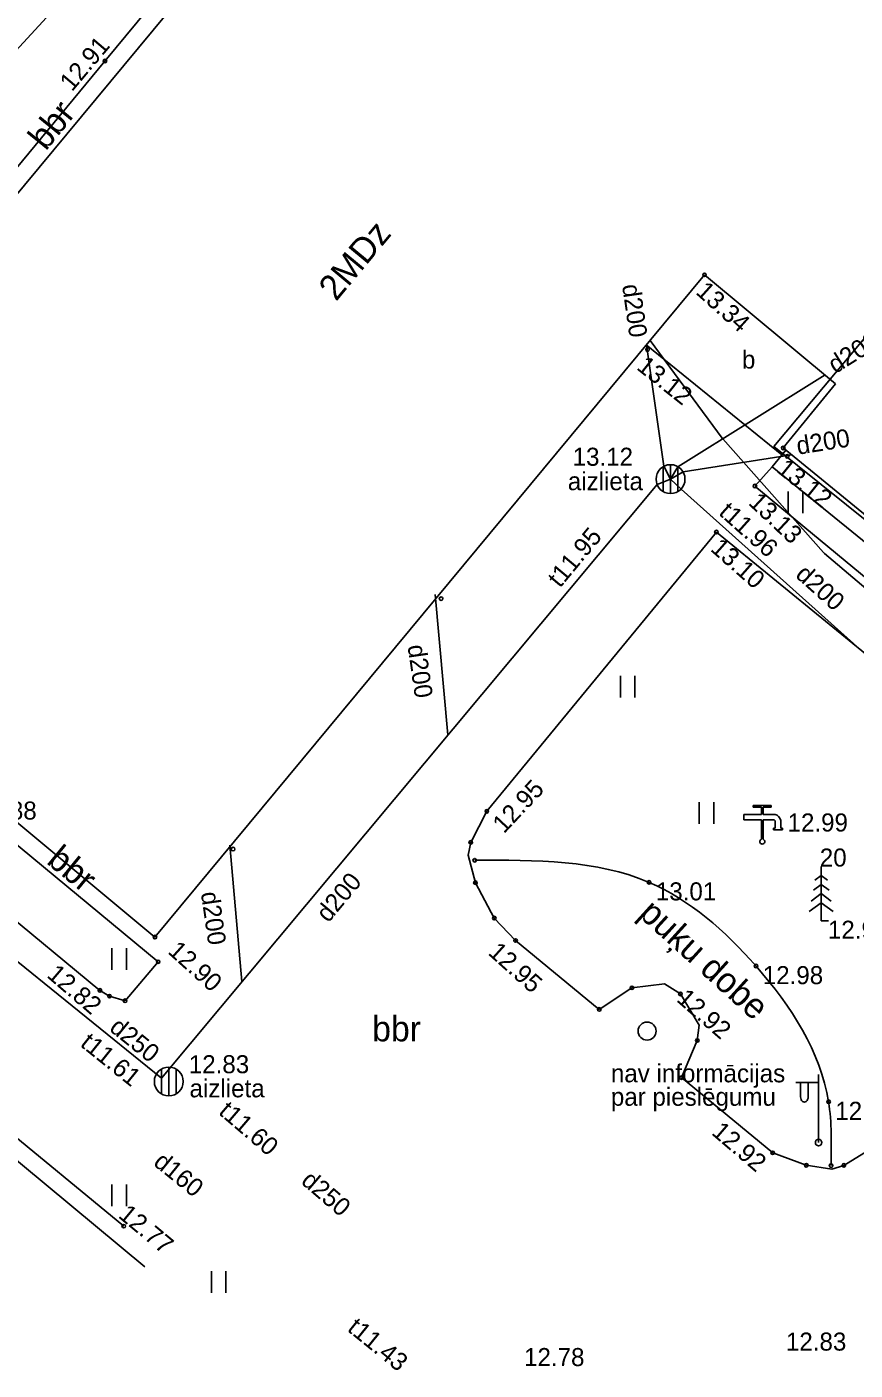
# Model space of a CAD drawing. Extents: x 503877 to 504025, y 304562 to 304725.
# Drawn here: x 503910.05 to 503933, y 304561.87 to 304599.07 of the extents above; entities that cross this region are included whole.
import ezdxf

# ---------------------------------------------------------------- set-up
doc = ezdxf.new("R2010")
doc.units = 0
for name, color, linetype in [('42', 7, 'Continuous'), ('APGS_ELEM_####_####_#', 7, 'Continuous'), ('APGS_ELEM_####_TKST_#', 7, 'Continuous'), ('BUVE_BDET_####_####_#', 7, 'Continuous'), ('BUVE_BDET_####_TKST_#', 7, 'Continuous'), ('BUVE_EKAS_####_####_#', 7, 'Continuous'), ('BUVE_EKAS_ADRS_TKST_#', 7, 'Continuous'), ('BUVE_ELEM_####_####_#', 7, 'Continuous'), ('CELI_CMAL_####_####_#', 7, 'Continuous'), ('CELI_CSEG_####_TKST_#', 7, 'Continuous'), ('ELEK_VADP_ZSPR_####_#', 7, 'Continuous'), ('LKAN_ELEM_####_####_#', 7, 'Continuous'), ('LKAN_ELEM_PAST_TKST_#', 7, 'Continuous'), ('LKAN_VADP_PAST_####_#', 7, 'Continuous'), ('LKAN_VADP_PAST_TKST_#', 7, 'Continuous'), ('RELJ_AATZ_####_TKST_#', 7, 'Continuous'), ('RELJ_ELEM_####_####_#', 7, 'Continuous'), ('SKAN_ELEM_PAST_TKST_#', 7, 'Continuous'), ('SKAN_VADP_PAST_TKST_#', 7, 'Continuous'), ('TERT_DIAM_####_TKST_#', 7, 'Continuous'), ('TERT_ELEM_####_####_#', 7, 'Continuous'), ('TERT_IZMT_####_TKST_#', 7, 'Continuous'), ('TERT_KONT_####_####_#', 7, 'Continuous'), ('UDTK_ELEM_####_####_#', 7, 'Continuous'), ('UDTK_ELEM_####_TKST_#', 7, 'Continuous')]:
    doc.layers.add(name, color=color, linetype=linetype)

msp = doc.modelspace()

# ---------------------------------------------------------------- linework, layer by layer
at = {"layer": '42'}
msp.add_lwpolyline([(503940.294, 304598.947), (503951.661, 304589.773), (503949.864, 304587.645), (503954.733, 304583.621), (503953.927, 304582.557), (503960.49, 304577.208), (503958.987, 304575.41), (503959.865, 304574.697), (503955.838, 304569.828), (503955.063, 304570.502), (503953.67, 304568.891), (503946.74, 304574.542), (503947.217, 304575.092), (503942.561, 304578.835), (503942.084, 304578.358), (503930.754, 304587.457), (503939.344, 304597.708)], close=True, dxfattribs=at)
at = {"layer": 'APGS_ELEM_####_####_#'}
for p, q in [((503931.992, 304569.841), (503931.357, 304569.836)), ((503931.492, 304569.837), (503931.492, 304569.445)), ((503931.702, 304569.839), (503931.702, 304569.445)), ((503931.992, 304568.174), (503931.992, 304570.057))]:
    msp.add_line(p, q, dxfattribs=at)
msp.add_circle((503931.992, 304568.174), 0.09, dxfattribs=at)
msp.add_ellipse((503931.597, 304569.445), major_axis=(0, 0.151), ratio=0.695971, start_param=1.570796, end_param=4.712389, dxfattribs=at)
at = {"layer": 'BUVE_BDET_####_####_#'}
for p, q in [((503930.975, 304587.224), (503927.218, 304590.266)), ((503931.081, 304587.355), (503930.703, 304586.889)), ((503941.788, 304577.888), (503930.703, 304586.889))]:
    msp.add_line(p, q, dxfattribs=at)
at = {"layer": 'BUVE_EKAS_####_####_#'}
for p, q in [((503924.556, 304612.247), (503901.224, 304584.141)), ((503913.603, 304573.865), (503928.83, 304592.208)), ((503932.464, 304589.191), (503928.83, 304592.208)), ((503932.464, 304589.191), (503931.011, 304587.412)), ((503942.277, 304578.21), (503931.011, 304587.412)), ((503908.794, 304577.857), (503913.603, 304573.865)), ((503904.187, 304572.307), (503913.325, 304564.734))]:
    msp.add_line(p, q, dxfattribs=at)
at = {"layer": 'BUVE_ELEM_####_####_#'}
msp.add_circle((503927.24, 304571.263), 0.25, dxfattribs=at)
at = {"layer": 'CELI_CMAL_####_####_#'}
for p, q in [((503912.215, 304598.126), (503924.433, 304612.895)), ((503921.326, 304610.998), (503899.68, 304587.482)), ((503901.003, 304584.612), (503912.215, 304598.126)), ((503930.227, 304586.356), (503930.703, 304586.889)), ((503941.255, 304577.235), (503930.227, 304586.356)), ((503922.799, 304577.351), (503929.16, 304585.083)), ((503929.16, 304585.083), (503940.23, 304576.035)), ((503913.691, 304573.18), (503906.103, 304579.453)), ((503904.812, 304578.39), (503912.077, 304572.389)), ((503922.799, 304577.351), (503922.354, 304576.49)), ((503922.354, 304576.49), (503922.28, 304576.131)), ((503922.28, 304576.131), (503922.483, 304575.373)), ((503922.483, 304575.373), (503923.005, 304574.392)), ((503923.005, 304574.392), (503923.594, 304573.772)), ((503923.594, 304573.772), (503925.914, 304571.863)), ((503912.775, 304572.103), (503913.691, 304573.18)), ((503904.097, 304572.983), (503912.739, 304565.859)), ((503912.077, 304572.389), (503912.343, 304572.23)), ((503925.914, 304571.863), (503926.818, 304572.461)), ((503926.818, 304572.461), (503927.723, 304572.575)), ((503927.723, 304572.575), (503928.164, 304572.292)), ((503912.343, 304572.23), (503912.775, 304572.103)), ((503928.164, 304572.292), (503928.678, 304571.43)), ((503928.678, 304571.43), (503928.63, 304571.001)), ((503928.63, 304571.001), (503928.192, 304569.973)), ((503930.721, 304567.89), (503928.192, 304569.973)), ((503933.951, 304568.323), (503932.691, 304567.544)), ((503931.65, 304567.547), (503930.721, 304567.89)), ((503932.362, 304567.437), (503931.65, 304567.547)), ((503932.691, 304567.544), (503932.362, 304567.437))]:
    msp.add_line(p, q, dxfattribs=at)
at = {"layer": 'ELEK_VADP_ZSPR_####_#'}
for p, q in [((503929.324, 304587.688), (503927.329, 304590.386)), ((503929.341, 304587.667), (503929.324, 304587.688)), ((503932.126, 304584.518), (503929.341, 304587.667)), ((503932.157, 304584.487), (503932.126, 304584.518)), ((503942.397, 304575.823), (503932.157, 304584.487))]:
    msp.add_line(p, q, dxfattribs=at)
at = {"layer": 'LKAN_ELEM_####_####_#'}
for p, q in [((503927.689, 304586.203), (503927.689, 304586.895)), ((503927.889, 304586.149), (503927.889, 304586.949)), ((503928.089, 304586.203), (503928.089, 304586.895)), ((503913.786, 304569.52), (503913.786, 304570.212)), ((503913.986, 304569.466), (503913.986, 304570.266)), ((503914.186, 304569.52), (503914.186, 304570.212))]:
    msp.add_line(p, q, dxfattribs=at)
for centre in [(503927.889, 304586.549), (503913.986, 304569.866)]:
    msp.add_circle(centre, 0.4, dxfattribs=at)
at = {"layer": 'LKAN_VADP_PAST_####_#'}
for p, q in [((503927.704, 304586.904), (503927.221, 304590.267)), ((503928.094, 304586.893), (503932.17, 304589.435)), ((503927.704, 304586.904), (503927.889, 304586.549)), ((503927.889, 304586.549), (503928.094, 304586.893)), ((503931.24, 304587.225), (503928.235, 304586.75)), ((503927.516, 304586.405), (503927.889, 304586.549)), ((503927.889, 304586.549), (503928.235, 304586.75)), ((503927.889, 304586.549), (503928.18, 304586.275)), ((503927.516, 304586.405), (503913.78, 304569.963)), ((503939.435, 304576.189), (503928.18, 304586.275)), ((503921.72, 304579.467), (503921.371, 304583.357)), ((503916.014, 304572.637), (503915.676, 304576.409)), ((503913.78, 304569.963), (503906.982, 304575.455))]:
    msp.add_line(p, q, dxfattribs=at)
at = {"layer": 'RELJ_ELEM_####_####_#'}
for centre in [(503912.215, 304598.126), (503928.83, 304592.208), (503927.251, 304590.137), (503931.011, 304587.412), (503931.122, 304587.184), (503930.227, 304586.356), (503929.16, 304585.083), (503921.532, 304583.239), (503922.799, 304577.351), (503922.354, 304576.49), (503915.768, 304576.303), (503922.462, 304575.993), (503922.483, 304575.373), (503927.296, 304575.382), (503923.005, 304574.392), (503913.603, 304573.865), (503923.594, 304573.772), (503913.691, 304573.18), (503930.259, 304573.062), (503912.077, 304572.389), (503926.818, 304572.461), (503912.343, 304572.23), (503912.775, 304572.103), (503928.164, 304572.292), (503925.914, 304571.863), (503928.63, 304571.001), (503928.192, 304569.973), (503932.268, 304569.304), (503930.721, 304567.89), (503931.65, 304567.547), (503932.337, 304567.537), (503932.691, 304567.544), (503912.739, 304565.859)]:
    msp.add_circle(centre, 0.05, dxfattribs=at)
at = {"layer": 'TERT_ELEM_####_####_#'}
for p, q in [((503931.152, 304585.604), (503931.152, 304586.204)), ((503931.552, 304585.604), (503931.552, 304586.204)), ((503926.5, 304580.5), (503926.5, 304581.1)), ((503926.9, 304580.5), (503926.9, 304581.1)), ((503928.686, 304577), (503928.686, 304577.6)), ((503929.086, 304577), (503929.086, 304577.6)), ((503932.064, 304575.819), (503932.064, 304574.319)), ((503932.064, 304575.569), (503931.888, 304575.441)), ((503932.064, 304575.569), (503932.238, 304575.441)), ((503932.064, 304575.069), (503931.786, 304574.865)), ((503932.064, 304575.319), (503931.848, 304575.161)), ((503932.064, 304575.319), (503932.28, 304575.161)), ((503932.064, 304575.069), (503932.342, 304574.865)), ((503932.064, 304574.819), (503931.732, 304574.575)), ((503932.064, 304574.819), (503932.398, 304574.575)), ((503932.064, 304574.319), (503932.264, 304574.319)), ((503912.41, 304572.958), (503912.41, 304573.558)), ((503912.81, 304572.958), (503912.81, 304573.558)), ((503912.41, 304566.411), (503912.41, 304567.011)), ((503912.81, 304566.411), (503912.81, 304567.011)), ((503915.169, 304564.01), (503915.169, 304564.61)), ((503915.569, 304564.01), (503915.569, 304564.61))]:
    msp.add_line(p, q, dxfattribs=at)
at = {"layer": 'TERT_KONT_####_####_#'}
msp.add_spline([(503932.337, 304567.537), (503932.268, 304569.304), (503930.259, 304573.062), (503927.296, 304575.382), (503922.462, 304575.993)], degree=3, dxfattribs=at)
at = {"layer": 'UDTK_ELEM_####_####_#'}
for p, q in [((503929.919, 304577.261), (503930.405, 304577.261)), ((503929.919, 304577.111), (503929.919, 304577.261)), ((503930.18, 304577.461), (503930.18, 304577.511)), ((503930.18, 304577.511), (503930.68, 304577.511)), ((503930.405, 304577.461), (503930.18, 304577.461)), ((503930.405, 304577.261), (503930.405, 304577.461)), ((503930.68, 304577.461), (503930.455, 304577.461)), ((503930.455, 304577.461), (503930.455, 304577.261)), ((503930.455, 304577.261), (503930.791, 304577.261)), ((503930.68, 304577.511), (503930.68, 304577.461)), ((503930.405, 304577.111), (503929.919, 304577.111)), ((503930.405, 304576.575), (503930.405, 304577.111)), ((503930.761, 304577.111), (503930.455, 304577.111)), ((503930.455, 304577.111), (503930.455, 304576.575)), ((503930.741, 304576.837), (503930.741, 304576.887)), ((503930.741, 304576.887), (503930.791, 304576.887)), ((503930.991, 304576.837), (503930.741, 304576.837)), ((503930.791, 304576.887), (503930.791, 304577.082)), ((503930.941, 304577.111), (503930.941, 304576.887)), ((503930.941, 304576.887), (503930.991, 304576.887)), ((503930.991, 304576.887), (503930.991, 304576.837))]:
    msp.add_line(p, q, dxfattribs=at)
for centre, radius, start, end in [((503930.722, 304577.043), 0.229, 17.4344, 72.5656), ((503930.722, 304577.043), 0.0792, 29.8818, 60.1182), ((503930.43, 304576.511), 0.069, 111.235, 68.765)]:
    msp.add_arc(centre, radius, start, end, dxfattribs=at)

# ---------------------------------------------------------------- texts
at = {"layer": 'APGS_ELEM_####_TKST_#'}
for s, p in [('nav informācijas', (503926.236, 304569.844)), ('par pieslēgumu', (503926.236, 304569.194))]:
    msp.add_text(s, height=0.5, dxfattribs=at).set_placement(p)
at = {"layer": 'BUVE_BDET_####_TKST_#'}
msp.add_text('b', height=0.5, dxfattribs=at).set_placement((503929.868, 304589.611))
at = {"layer": 'BUVE_EKAS_ADRS_TKST_#'}
msp.add_text('2MDz', height=0.7, rotation=50.3031, dxfattribs=at).set_placement((503918.622, 304591.453))
at = {"layer": 'CELI_CSEG_####_TKST_#'}
for rotation, p in [(50.9613, (503910.578, 304595.621)), (320.7718, (503910.57, 304575.924))]:
    msp.add_text('bbr', height=0.7, rotation=rotation, dxfattribs=at).set_placement(p)
msp.add_text('bbr', height=0.7, dxfattribs=at).set_placement((503919.621, 304570.979))
at = {"layer": 'LKAN_ELEM_PAST_TKST_#'}
for s, p in [(' 13.12', (503924.991, 304586.919)), (' 12.83', (503914.355, 304570.095)), (' 12.83', (503930.901, 304562.413)), (' 12.78', (503923.645, 304561.984))]:
    msp.add_text(s, height=0.5, dxfattribs=at).set_placement(p)
at = {"layer": 'LKAN_VADP_PAST_TKST_#'}
for s, rotation, p in [('d200', 278.1886, (503926.546, 304591.916)), ('d200', 31.9528, (503932.455, 304589.455)), ('d200', 8.9927, (503931.419, 304587.224)), ('t11.96', 318.1348, (503929.197, 304585.589)), ('t11.95', 50.1243, (503924.824, 304583.516)), ('d200', 318.1348, (503931.322, 304583.859)), ('d200', 278.1886, (503920.601, 304581.932)), ('d200', 50.1243, (503918.406, 304574.244)), ('d200', 278.1886, (503914.874, 304575.091)), ('d250', 321.0658, (503912.311, 304571.296)), ('t11.61', 321.0658, (503911.503, 304570.867)), ('t11.60', 319.3792, (503915.338, 304568.987)), ('d250', 319.3792, (503917.623, 304567.062))]:
    msp.add_text(s, height=0.5, rotation=rotation, dxfattribs=at).set_placement(p)
at = {"layer": 'RELJ_AATZ_####_TKST_#'}
for s, rotation, p in [(' 12.91', 49.827, (503911.183, 304597.12)), (' 13.34', 317.9825, (503928.424, 304591.825)), (' 13.12', 321.5671, (503926.776, 304589.724)), (' 13.12', 321.1801, (503930.658, 304586.886)), (' 13.13', 316.9681, (503929.886, 304585.991)), (' 13.10', 318.5063, (503928.829, 304584.708)), (' 12.95', 46.7571, (503923.146, 304576.579)), (' 12.90', 317.9537, (503913.796, 304573.561)), (' 12.95', 318.0055, (503922.67, 304573.527)), (' 12.82', 319.3685, (503910.438, 304572.898)), (' 12.92', 318.8176, (503927.889, 304572.229)), (' 12.92', 319.4439, (503928.857, 304568.54)), (' 12.77', 320.2409, (503912.419, 304566.239))]:
    msp.add_text(s, height=0.5, rotation=rotation, dxfattribs=at).set_placement(p)
for s, p in [(' 12.88', (503908.467, 304577.12)), (' 13.01', (503927.296, 304574.882)), (' 12.98', (503932.064, 304573.819)), (' 12.98', (503930.259, 304572.562)), (' 12.98', (503932.268, 304568.804))]:
    msp.add_text(s, height=0.5, dxfattribs=at).set_placement(p)
at = {"layer": 'SKAN_ELEM_PAST_TKST_#'}
for p in [(503925.043, 304586.242), (503914.561, 304569.428)]:
    msp.add_text('aizlieta', height=0.5, dxfattribs=at).set_placement(p)
at = {"layer": 'SKAN_VADP_PAST_TKST_#'}
for s, p in [('d160', (503913.531, 304567.571)), ('t11.43', (503918.905, 304562.979))]:
    msp.add_text(s, height=0.5, rotation=320.973, dxfattribs=at).set_placement(p)
at = {"layer": 'TERT_DIAM_####_TKST_#'}
msp.add_text(' 20', height=0.5, dxfattribs=at).set_placement((503931.839, 304575.819))
at = {"layer": 'TERT_IZMT_####_TKST_#'}
msp.add_text('puķu dobe', height=0.7, rotation=317.7627, dxfattribs=at).set_placement((503926.973, 304574.464))
at = {"layer": 'UDTK_ELEM_####_TKST_#'}
msp.add_text(' 12.99', height=0.5, dxfattribs=at).set_placement((503930.946, 304576.79))

doc.saveas('drawing.dxf')
